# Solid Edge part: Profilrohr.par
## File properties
Username: bmolnar
Dokumentum tartalom típus: 0
Author: bmolnar
Last saved by: bmolnar
Revision: 81
Sűrűség: 0,000 kg/m^3
Pontosság: 0,990
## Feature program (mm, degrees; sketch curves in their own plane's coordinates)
base feature "unnamed BaseFeature 1"
thread "unnamed Thread 1"
thread "Menet_2"  ThreadDepth = 6 mm
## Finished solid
Body 1: solid body, 143 faces, 298 edges, 189 vertices, 3 separate solids.
  Faces by surface: plane 62, cylinder 61, cone 16, torus 4
  Edges by curve: line 156, circle 138, curve on surface 2, spline 2
Bounding box of the edges (mm; curved faces can reach further): 46.000 x 51.000 x 64.500, from (-23, -24, 0) to (23, 27, 64.5).
Cylindrical faces by radius (mm): R0.3 x24, R0.8 x2, R2.5 x2, R2.9 x8, R4.283 x4, R4.35 x2, R4.4 x6, R4.5 x2, R16 x1, R16.85 x2, R17.05 x2, R17.9 x2, R30 x4
Conical faces (half-angle, radius in mm at the cone's reference point): 21 deg R16.325 x2, 30 deg R4.0613 x2, 45 deg R2.75 x4, 45 deg R4.1 x2, 45 deg R4.783 x2, 45 deg R17.1 x2, 45 deg R17.15 x2
Toroidal faces (ring radius, tube radius in mm): R17.7 r0.2 x4
Planar faces by outward normal: +x 6, +y 9, +z 10, -x 6, -y 5, -z 10, oblique 16
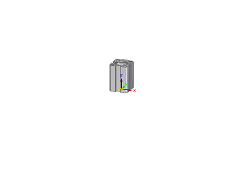
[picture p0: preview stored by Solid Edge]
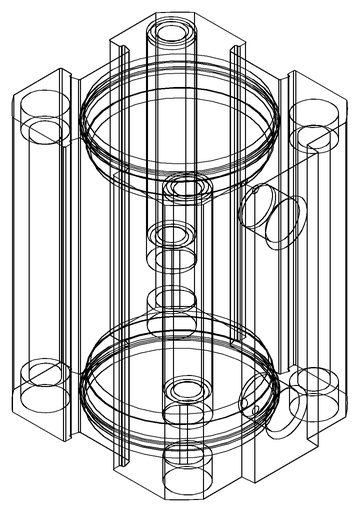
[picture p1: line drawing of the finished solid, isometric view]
